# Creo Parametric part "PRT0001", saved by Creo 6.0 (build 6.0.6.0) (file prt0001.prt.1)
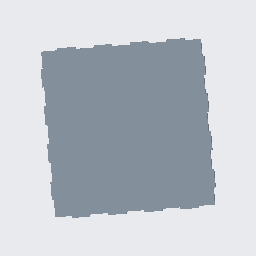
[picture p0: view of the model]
Units: Inch lbm Second (Pro/E Default); INCH, POUND, SECS

Created from: INLBS_PART_SOLID.PRT

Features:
  1. datum plane "RIGHT"
  2. datum plane "TOP"
  3. datum plane "FRONT"
  4. coordinate system
  5. sketch "Sketch 1"
  6. extrusion "Extrude 1"

Surfaces: 70 plane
